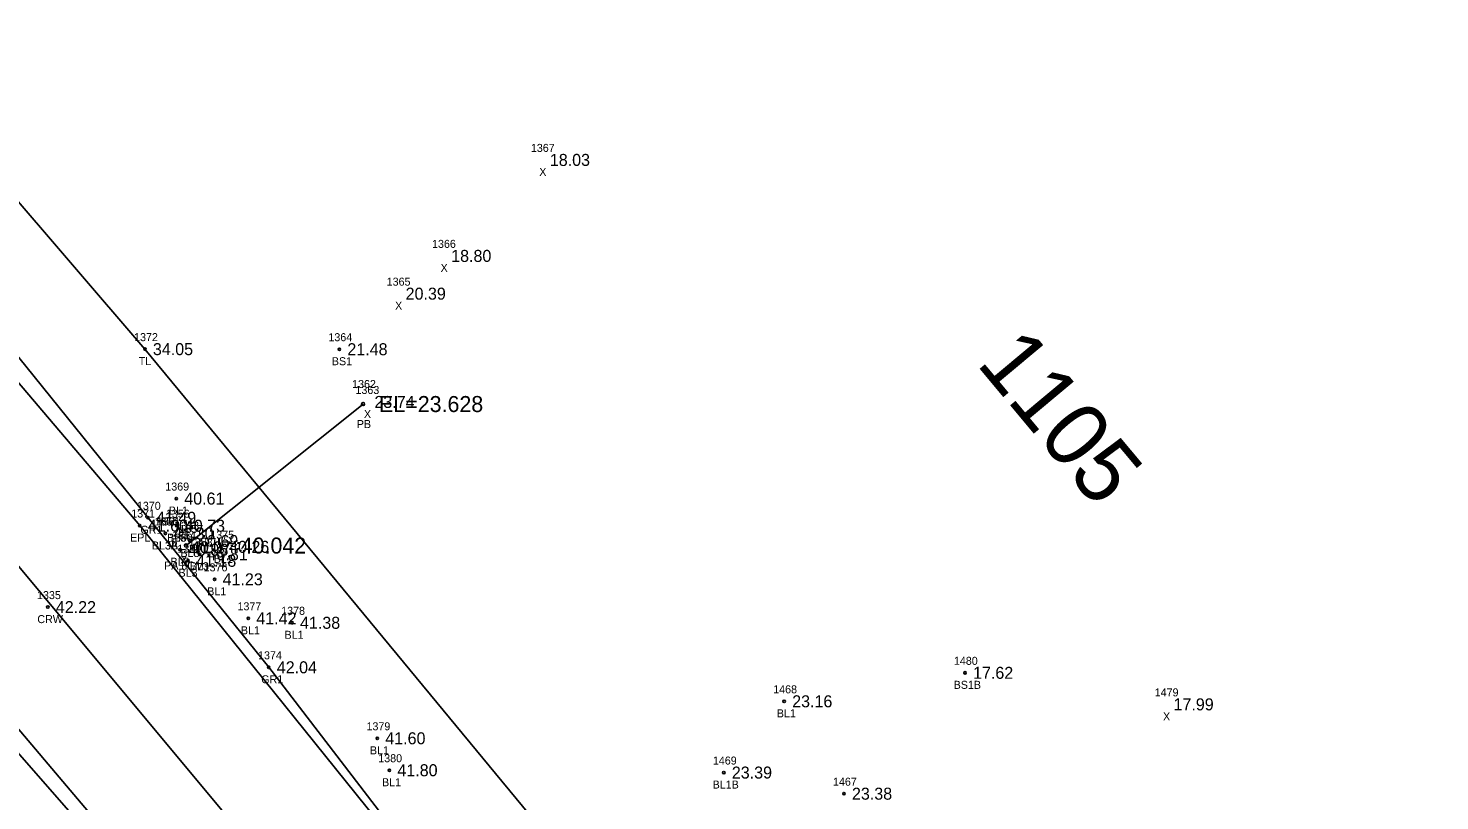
# Model space of a CAD drawing. Extents: x 2042117 to 2045853, y 303080 to 309569.
# Drawn here: x 2043361.9 to 2043538.3, y 306002.5 to 306099 of the extents above; entities that cross this region are included whole.
import ezdxf

# ---------------------------------------------------------------- set-up
doc = ezdxf.new("R2010")
doc.units = 0
for name, color, linetype in [('RD_DTM_BkLn_txCode', 7, 'Continuous'), ('RD_EX_DR_Pipe', 7, 'Continuous'), ('RD_EX_DR_Pipe_txCode', 7, 'Continuous'), ('RD_EX_GuardRail', 7, 'Continuous'), ('RD_EX_GuardRail_txCode', 7, 'Continuous'), ('RD_EX_Misc_txCode', 7, 'Continuous'), ('RD_EX_Road', 7, 'Continuous'), ('RD_EX_Road_txCode', 7, 'Continuous'), ('RD_EX_TX_GuardRail_ELEV', 7, 'Continuous'), ('RD_EX_TX_Misc_ELEV', 7, 'Continuous'), ('RD_EX_TX_Road_ELEV', 7, 'Continuous'), ('RD_EX_TX_VEG_ELEV', 7, 'Continuous'), ('RD_EX_VEG', 7, 'Continuous'), ('RD_EX_VEG_txCode', 7, 'Continuous'), ('RD_HC_Cl', 7, 'Continuous'), ('RD_HC_Survey_ELEV', 7, 'Continuous'), ('RD_HC_Survey_txCode', 7, 'Continuous'), ('RD_HC_TX_Sta50', 7, 'Continuous'), ('RD_SMD_Locator', 7, 'Continuous'), ('RD_TX_Pipe_ElevEX', 7, 'Continuous')]:
    doc.layers.add(name, color=color, linetype=linetype)

msp = doc.modelspace()

# ---------------------------------------------------------------- linework, layer by layer
at = {"layer": 'RD_EX_DR_Pipe'}
msp.add_line((2043381.64, 306034.36), (2043403.76, 306052.04), dxfattribs=at)
at = {"layer": 'RD_EX_GuardRail'}
for points in [[(2042989.52, 306565.65), (2042994.63, 306555.31), (2043016.03, 306510.44), (2043038.99, 306465.35), (2043062.42, 306421.45), (2043086.95, 306378), (2043112.8, 306335.35), (2043139.38, 306293.6), (2043167.12, 306252.13), (2043196.01, 306211.01), (2043226.01, 306171.01), (2043257.1, 306132.34), (2043288.76, 306093.67), (2043353.25, 306016.86), (2043419.08, 305941.69), (2043443.37, 305914.98)], [(2043328.2, 306098.11), (2043376.89, 306037.83), (2043391.98, 306019.15), (2043438.03, 305959.17), (2043441.35, 305955), (2043457.81, 305935.14)]]:
    msp.add_lwpolyline(points, dxfattribs=at)
at = {"layer": 'RD_EX_Road'}
for points in [[(2043137.38, 306350.66), (2043162.88, 306309.77), (2043190.74, 306268.8), (2043219.18, 306228.69), (2043249.32, 306189.21), (2043279.47, 306150.9), (2043310.9, 306113.33), (2043375.86, 306036.86), (2043413.21, 305990.46), (2043437.78, 305959.09), (2043453.01, 305940), (2043456.21, 305936.08), (2043457.42, 305934.8)], [(2043115.12, 306336.87), (2043141.61, 306295.02), (2043169.3, 306253.51), (2043198.36, 306212.75), (2043228.29, 306172.85), (2043259.02, 306133.68), (2043290.73, 306095.31), (2043354.79, 306018.38), (2043419.43, 305942.01), (2043438.08, 305920.77), (2043442.86, 305915.34)]]:
    msp.add_lwpolyline(points, dxfattribs=at)
at = {"layer": 'RD_EX_VEG'}
msp.add_lwpolyline([(2043030.11, 306588.1), (2043035.72, 306574.19), (2043060.12, 306522.02), (2043088.59, 306466.9), (2043098.93, 306441.29), (2043120.97, 306400.06), (2043177.31, 306317.21), (2043201.76, 306279.58), (2043229.83, 306237.41), (2043260.65, 306197.8), (2043289.37, 306160.32), (2043322.23, 306122.17), (2043376.5, 306058.9), (2043456.79, 305961.76), (2043477.52, 305946.76)], dxfattribs=at)
at = {"layer": 'RD_HC_Cl'}
msp.add_line((2043284.3, 306123.24), (2045221.31, 303804), dxfattribs=at)
at = {"layer": 'RD_SMD_Locator'}
for centre, radius in [((2043376.5, 306058.9), 0.15), ((2043400.8, 306058.89), 0.15), ((2043403.76, 306052.04), 0.2), ((2043380.42, 306040.23), 0.15), ((2043376.89, 306037.83), 0.15), ((2043375.86, 306036.86), 0.15), ((2043379.06, 306035.87), 0.15), ((2043379.06, 306035.87), 0.15), ((2043380.49, 306036.84), 0.15), ((2043381.64, 306034.36), 0.2), ((2043382.15, 306034.93), 0.15), ((2043386.02, 306034.2), 0.15), ((2043380.9, 306033.84), 0.15), ((2043381.9, 306032.46), 0.15), ((2043383.33, 306033.28), 0.15), ((2043385.21, 306030.14), 0.15), ((2043364.37, 306026.67), 0.15), ((2043389.42, 306025.27), 0.15), ((2043394.88, 306024.71), 0.15), ((2043391.98, 306019.15), 0.15), ((2043478.98, 306018.46), 0.15), ((2043456.38, 306014.9), 0.15), ((2043405.54, 306010.28), 0.15), ((2043407.05, 306006.29), 0.15), ((2043448.84, 306006), 0.15), ((2043463.85, 306003.36), 0.15)]:
    msp.add_circle(centre, radius, dxfattribs=at)

# ---------------------------------------------------------------- texts
at = {"layer": 'RD_DTM_BkLn_txCode'}
for s, p in [('1364', (2043399.43, 306059.89)), ('BS1', (2043399.86, 306056.89)), ('1369', (2043379.05, 306041.23)), ('1355', (2043377.71, 306036.87)), ('1361', (2043377.97, 306036.87)), ('1356', (2043379.12, 306037.84)), ('BL1', (2043379.5, 306038.23)), ('1357', (2043380.8, 306035.93)), ('1375', (2043384.67, 306035.2)), ('BL3A', (2043377.36, 306033.87)), ('BL3B', (2043377.38, 306033.87)), ('BL3', (2043379.29, 306034.84)), ('1360', (2043379.49, 306034.84)), ('1359', (2043380.56, 306033.46)), ('1358', (2043381.98, 306034.28)), ('BL3', (2043379.7, 306031.84)), ('BL3', (2043380.94, 306032.93)), ('BL1', (2043385.1, 306032.2)), ('BL3', (2043380.7, 306030.46)), ('BL3', (2043382.12, 306031.28)), ('1376', (2043383.84, 306031.14)), ('BL1', (2043384.29, 306028.14)), ('1377', (2043388.07, 306026.27)), ('1378', (2043393.53, 306025.71)), ('BL1', (2043388.49, 306023.27)), ('BL1', (2043393.95, 306022.71)), ('1480', (2043477.59, 306019.46)), ('1468', (2043455.01, 306015.9)), ('BS1B', (2043477.56, 306016.46)), ('BL1', (2043455.46, 306012.9)), ('1379', (2043404.19, 306011.28)), ('BL1', (2043404.62, 306008.28)), ('1380', (2043405.66, 306007.29)), ('1469', (2043447.47, 306007)), ('BL1', (2043406.13, 306004.29)), ('BL1B', (2043447.44, 306004)), ('1467', (2043462.48, 306004.36))]:
    msp.add_text(s, height=1, dxfattribs=at).set_placement(p)
at = {"layer": 'RD_EX_DR_Pipe_txCode'}
for s, p in [('1362', (2043402.39, 306054.04)), ('PB', (2043402.98, 306049.04)), ('1353', (2043380.29, 306036.36)), ('PA 8CM', (2043378.9, 306031.36))]:
    msp.add_text(s, height=1, dxfattribs=at).set_placement(p)
at = {"layer": 'RD_EX_GuardRail_txCode'}
for s, p in [('1370', (2043375.5, 306038.83)), ('GR1', (2043375.94, 306035.83)), ('1374', (2043390.64, 306020.15)), ('GR1', (2043391.04, 306017.15))]:
    msp.add_text(s, height=1, dxfattribs=at).set_placement(p)
at = {"layer": 'RD_EX_Misc_txCode'}
for s, p in [('1367', (2043424.73, 306083.54)), ('X', (2043425.78, 306080.54)), ('1366', (2043412.38, 306071.55)), ('X', (2043413.45, 306068.55)), ('1365', (2043406.71, 306066.83)), ('X', (2043407.76, 306063.83)), ('1363', (2043402.81, 306053.3)), ('X', (2043403.87, 306050.3)), ('1354', (2043379.91, 306035.14)), ('X', (2043380.94, 306032.14)), ('1479', (2043502.68, 306015.52)), ('X', (2043503.72, 306012.52))]:
    msp.add_text(s, height=1, dxfattribs=at).set_placement(p)
at = {"layer": 'RD_EX_Road_txCode'}
for s, p in [('1371', (2043374.79, 306037.86)), ('EPL', (2043374.65, 306034.86))]:
    msp.add_text(s, height=1, dxfattribs=at).set_placement(p)
at = {"layer": 'RD_EX_TX_GuardRail_ELEV'}
for s, p in [('41.49', (2043377.89, 306037.08)), ('42.04', (2043392.98, 306018.4))]:
    msp.add_text(s, height=1.5, dxfattribs=at).set_placement(p)
at = {"layer": 'RD_EX_TX_Misc_ELEV'}
for s, p in [('18.03', (2043427.1, 306081.79)), ('18.80', (2043414.77, 306069.8)), ('20.39', (2043409.08, 306065.08)), ('21.48', (2043401.8, 306058.14)), ('23.74', (2043405.18, 306051.55)), ('40.61', (2043381.42, 306039.48)), ('41.30', (2043380.06, 306035.12)), ('41.30', (2043380.06, 306035.12)), ('40.73', (2043381.49, 306036.09)), ('40.96', (2043381.9, 306033.09)), ('40.07', (2043382.26, 306033.39)), ('40.69', (2043383.15, 306034.18)), ('40.26', (2043387.02, 306033.45)), ('41.18', (2043382.9, 306031.71)), ('40.81', (2043384.33, 306032.53)), ('41.23', (2043386.21, 306029.39)), ('41.42', (2043390.42, 306024.52)), ('41.38', (2043395.88, 306023.96)), ('17.62', (2043479.98, 306017.71)), ('23.16', (2043457.38, 306014.15)), ('17.99', (2043505.03, 306013.77)), ('41.60', (2043406.54, 306009.53)), ('41.80', (2043408.05, 306005.54)), ('23.39', (2043449.84, 306005.25)), ('23.38', (2043464.85, 306002.61))]:
    msp.add_text(s, height=1.5, dxfattribs=at).set_placement(p)
at = {"layer": 'RD_EX_TX_Road_ELEV'}
msp.add_text('41.60', height=1.5, dxfattribs=at).set_placement((2043376.86, 306036.11))
at = {"layer": 'RD_EX_TX_VEG_ELEV'}
msp.add_text('34.05', height=1.5, dxfattribs=at).set_placement((2043377.5, 306058.15))
at = {"layer": 'RD_EX_VEG_txCode'}
for s, p in [('1372', (2043375.15, 306059.9)), ('TL', (2043375.73, 306056.9))]:
    msp.add_text(s, height=1, dxfattribs=at).set_placement(p)
at = {"layer": 'RD_HC_Survey_ELEV'}
msp.add_text('42.22', height=1.5, dxfattribs=at).set_placement((2043365.37, 306025.92))
at = {"layer": 'RD_HC_Survey_txCode'}
for s, p in [('1335', (2043363.02, 306027.67)), ('CRW', (2043363.06, 306024.67))]:
    msp.add_text(s, height=1, dxfattribs=at).set_placement(p)
at = {"layer": 'RD_HC_TX_Sta50'}
msp.add_text('1105', height=8, rotation=309.8684, dxfattribs=at).set_placement((2043480.28, 306057.07))
at = {"layer": 'RD_TX_Pipe_ElevEX'}
for s, p in [('EL=23.628', (2043405.76, 306051.04)), ('EL=40.042', (2043383.64, 306033.36))]:
    msp.add_text(s, height=2, dxfattribs=at).set_placement(p)

doc.saveas('drawing.dxf')
